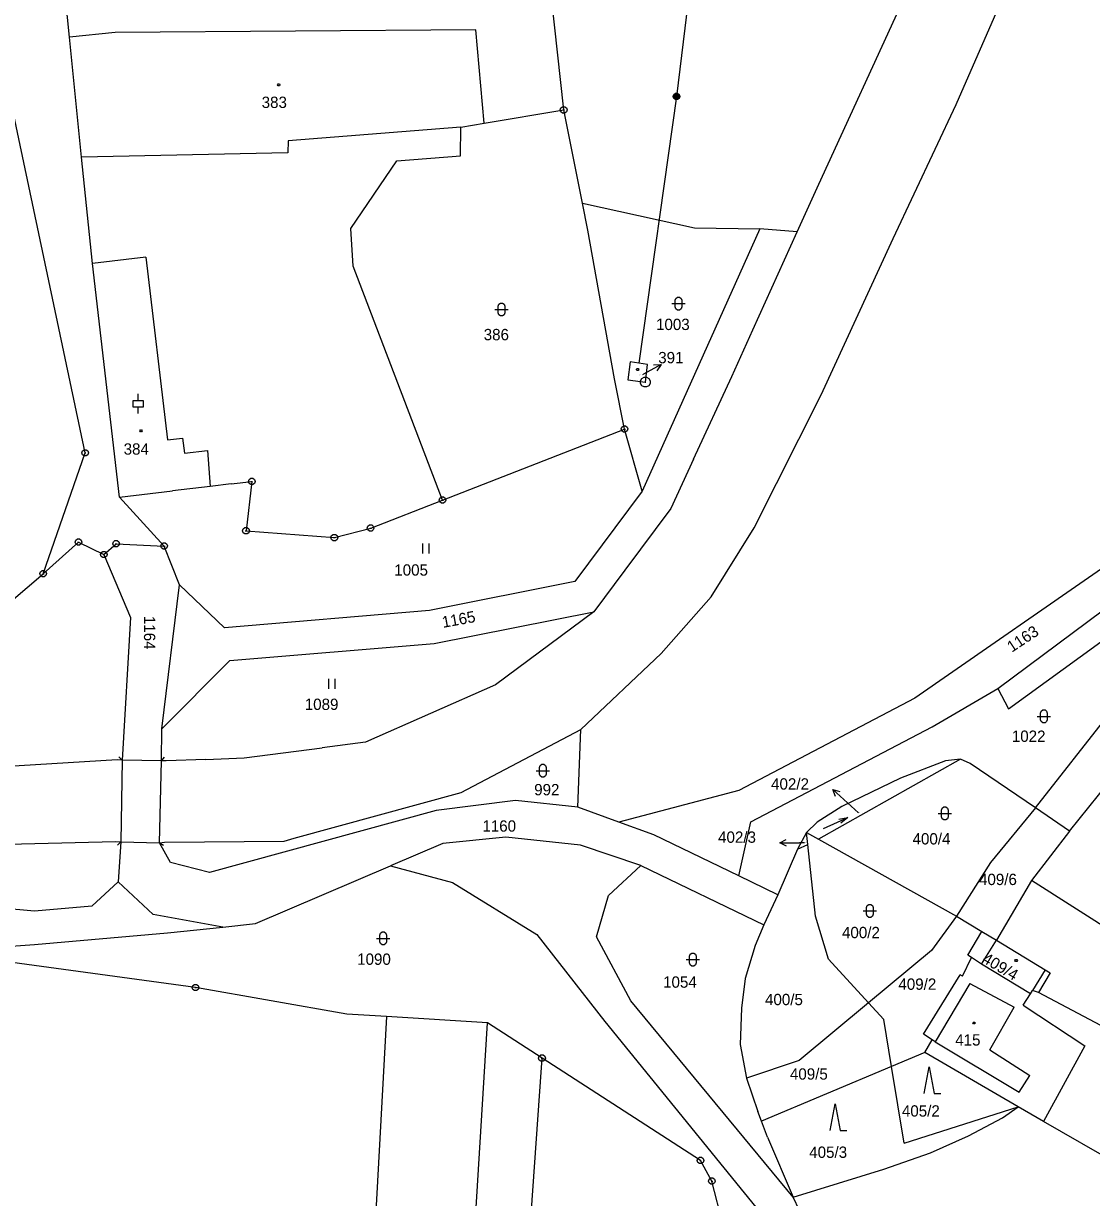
# Model space of a CAD drawing. Extents: x -812394 to -807601, y -1013098 to -1009266.
# Drawn here: x -810997.6 to -810837.1, y -1011688.8 to -1011512.4 of the extents above; entities that cross this region are included whole.
import ezdxf

# ---------------------------------------------------------------- set-up
doc = ezdxf.new("R2010")
doc.units = 0
for name, color, linetype in [('KN_HRANICE', 7, 'Continuous'), ('KN_KULTURY', 7, 'Continuous'), ('KN_MEZNIKY', 7, 'Continuous'), ('KN_PARCELY', 7, 'Continuous'), ('KN_SLUCKY', 7, 'Continuous'), ('KN_VEDENI', 7, 'Continuous')]:
    doc.layers.add(name, color=color, linetype=linetype)

# ---------------------------------------------------------------- blocks, each defined once
blk = doc.blocks.new('101')
blk.add_line((-0.05, 0), (0.05, 0))
blk.add_lwpolyline([(0.19, 0.72), (0.53, 0.53), (0.72, 0.19), (0.72, -0.2), (0.53, -0.54), (0.19, -0.73), (-0.2, -0.73), (-0.54, -0.54), (-0.73, -0.2), (-0.73, 0.19), (-0.54, 0.53), (-0.2, 0.72), (0.19, 0.72)])
blk = doc.blocks.new('306')
for p, q in [((-0.5, 1.5), (-0.5, 0)), ((0.5, 0), (0.5, 1.5))]:
    blk.add_line(p, q)
blk = doc.blocks.new('308')
blk.add_lwpolyline([(-0.75, 0), (0, 4), (0.75, 0), (1.75, 0)])
blk = doc.blocks.new('316')
for points in [[(-0.5, 1.5), (-0.4, 1.79), (-0.15, 1.97), (0.16, 1.97), (0.41, 1.79), (0.51, 1.5), (0.51, 0.5), (0.41, 0.21), (0.16, 0.03), (-0.15, 0.03), (-0.4, 0.21), (-0.5, 0.5), (-0.5, 1.5)], [(-1, 1), (0.27, 1), (1, 1)]]:
    blk.add_lwpolyline(points)
blk = doc.blocks.new('802')
blk.add_line((-3, 0), (3, 0))
blk.add_lwpolyline([(1, 0.5), (3, 0), (1, -0.5)])
blk = doc.blocks.new('10292')
blk.add_line((0, 3), (0, 0))
blk.add_lwpolyline([(-0.5, 2), (0, 3), (0.5, 2)])
blk = doc.blocks.new('318')
blk.add_line((0, 2), (0, 3))
blk.add_lwpolyline([(0, 0), (0, 1), (-0.75, 1), (-0.75, 2), (0, 2), (0.75, 2), (0.75, 1), (0, 1)])
blk = doc.blocks.new('105')
blk.add_line((-0.12, 0), (0.12, 0))
blk.add_lwpolyline([(0.15, 0.48), (0.4, 0.3), (0.5, 0.01), (0.4, -0.28), (0.15, -0.46), (-0.16, -0.46), (-0.41, -0.28), (-0.51, 0.01), (-0.41, 0.3), (-0.16, 0.48), (0.15, 0.48)])
blk = doc.blocks.new('4201')
blk.add_line((0, 0), (-0.5, -0.5))
blk = doc.blocks.new('601')
blk.add_lwpolyline([(-0.15, 0.48), (0.16, 0.48), (0.41, 0.3), (0.51, 0.01), (0.41, -0.28), (0.16, -0.46), (-0.15, -0.46), (-0.4, -0.28), (-0.5, 0.01), (-0.4, 0.3), (-0.15, 0.48), (-0.12, 0.44), (0.12, 0.44), (0.28, 0.36), (-0.28, 0.36), (-0.36, 0.28), (0.36, 0.28), (0.36, 0.2), (-0.36, 0.2), (-0.4, 0.12), (0.4, 0.12), (0.44, 0.04), (-0.44, 0.04), (-0.44, -0.04), (0.44, -0.04), (0.41, -0.12), (-0.4, -0.12), (-0.39, -0.2), (0.42, -0.2), (0.37, -0.28), (-0.35, -0.28), (-0.27, -0.36), (0.29, -0.36), (0.18, -0.44), (-0.16, -0.44)])
blk = doc.blocks.new('402')
blk.add_lwpolyline([(0.09, 0.15), (0.18, 0), (0.09, -0.15), (-0.09, -0.15), (-0.18, 0), (-0.09, 0.15), (0.09, 0.15)])

msp = doc.modelspace()

# ---------------------------------------------------------------- linework, layer by layer
at = {"layer": 'KN_HRANICE'}
for p, q in [((-810990.65, -1011514.5), (-810992.93, -1011491.98)), ((-810878.11, -1011536.55), (-810858.26, -1011493.31)), ((-810988.29, -1011576.92), (-811004.66, -1011499.57)), ((-810916.42, -1011525.41), (-810918.87, -1011502.5)), ((-810983.8, -1011513.77), (-810990.65, -1011514.5)), ((-810988.82, -1011532.52), (-810990.65, -1011514.5)), ((-810929.63, -1011513.38), (-810983.8, -1011513.77)), ((-810928.34, -1011527.4), (-810929.63, -1011513.38)), ((-810928.34, -1011527.4), (-810916.42, -1011525.41)), ((-810913.6, -1011539.41), (-810916.42, -1011525.41)), ((-810931.87, -1011527.99), (-810957.81, -1011530.07)), ((-810931.91, -1011532.3), (-810931.87, -1011527.99)), ((-810931.87, -1011527.99), (-810928.34, -1011527.4)), ((-810957.81, -1011530.07), (-810957.84, -1011531.83)), ((-810957.84, -1011531.83), (-810988.82, -1011532.52)), ((-810987.2, -1011548.48), (-810988.82, -1011532.52)), ((-810941.47, -1011533.07), (-810931.91, -1011532.3)), ((-810948.4, -1011543.24), (-810941.47, -1011533.07)), ((-810881.34, -1011543.7), (-810878.11, -1011536.55)), ((-810913.6, -1011539.41), (-810896.75, -1011543.11)), ((-810912.78, -1011543.48), (-810913.6, -1011539.41)), ((-810948.04, -1011548.87), (-810948.4, -1011543.24)), ((-810908.81, -1011565.82), (-810912.78, -1011543.48)), ((-810886.95, -1011543.28), (-810904.65, -1011582.69)), ((-810896.75, -1011543.11), (-810886.95, -1011543.28)), ((-810888.01, -1011558.44), (-810881.34, -1011543.7)), ((-810881.34, -1011543.7), (-810886.95, -1011543.28)), ((-810983.14, -1011583.56), (-810987.2, -1011548.48)), ((-810934.61, -1011584.01), (-810948.04, -1011548.87)), ((-810907.28, -1011573.34), (-810908.81, -1011565.82)), ((-810934.61, -1011584.01), (-810907.28, -1011573.34)), ((-810904.65, -1011582.69), (-810907.28, -1011573.34)), ((-810994.59, -1011595.07), (-810988.29, -1011576.92)), ((-810896.93, -1011577.89), (-810900.33, -1011585.26)), ((-810966.35, -1011581.58), (-810969.54, -1011581.95)), ((-810966.35, -1011581.58), (-810963.27, -1011581.22)), ((-810963.27, -1011581.22), (-810964.13, -1011588.63)), ((-810983.14, -1011583.56), (-810975.16, -1011582.61)), ((-810976.41, -1011590.91), (-810983.14, -1011583.56)), ((-810969.54, -1011581.95), (-810975.16, -1011582.61)), ((-810904.65, -1011582.69), (-810914.75, -1011596.26)), ((-810945.41, -1011588.22), (-810934.61, -1011584.01)), ((-810900.33, -1011585.26), (-810907.25, -1011594.56)), ((-810964.13, -1011588.63), (-810950.86, -1011589.65)), ((-810950.86, -1011589.65), (-810945.41, -1011588.22)), ((-810994.59, -1011595.07), (-810989.3, -1011590.32)), ((-810989.3, -1011590.32), (-810985.49, -1011592.2)), ((-810985.49, -1011592.2), (-810983.65, -1011590.57)), ((-810983.65, -1011590.57), (-810976.41, -1011590.91)), ((-810985.49, -1011592.2), (-810981.49, -1011601.67)), ((-810974.14, -1011596.72), (-810976.41, -1011590.91)), ((-810831.4, -1011591.35), (-810863.67, -1011613.78)), ((-811020.14, -1011616.85), (-810994.59, -1011595.07)), ((-810907.25, -1011594.56), (-810911.89, -1011600.79)), ((-810851.23, -1011612.3), (-810827.53, -1011594.64)), ((-810976.79, -1011618.38), (-810974.14, -1011596.72)), ((-810967.38, -1011603.18), (-810974.14, -1011596.72)), ((-810914.75, -1011596.26), (-810936.59, -1011600.58)), ((-810849.63, -1011615.36), (-810824.29, -1011596.97)), ((-810936.59, -1011600.58), (-810967.38, -1011603.18)), ((-810935.89, -1011605.54), (-810911.89, -1011600.79)), ((-810981.49, -1011601.67), (-810982.75, -1011623.07)), ((-810966.54, -1011608.13), (-810935.89, -1011605.54)), ((-810976.79, -1011618.38), (-810966.54, -1011608.13)), ((-810861.07, -1011618.06), (-810851.23, -1011612.3)), ((-810851.23, -1011612.3), (-810849.63, -1011615.36)), ((-810863.67, -1011613.78), (-810890.13, -1011627.65)), ((-810840.43, -1011633.72), (-810825.11, -1011614.6)), ((-810976.85, -1011623.16), (-810976.79, -1011618.38)), ((-810914.28, -1011630.13), (-810913.82, -1011618.49)), ((-810888.31, -1011632.34), (-810861.07, -1011618.06)), ((-810976.85, -1011623.16), (-810982.75, -1011623.07)), ((-810856.83, -1011622.91), (-810878.14, -1011634.96)), ((-810859.07, -1011623.17), (-810865.83, -1011625.76)), ((-810856.83, -1011622.91), (-810859.07, -1011623.17)), ((-810855.38, -1011623.6), (-810856.83, -1011622.91)), ((-810845.57, -1011630.24), (-810855.38, -1011623.6)), ((-810865.83, -1011625.76), (-810874.64, -1011630.05)), ((-810890.13, -1011627.65), (-810908.12, -1011632.39)), ((-810923.64, -1011629.14), (-810935.55, -1011630.66)), ((-810914.28, -1011630.13), (-810923.64, -1011629.14)), ((-810935.55, -1011630.66), (-810969.6, -1011639.97)), ((-810908.12, -1011632.39), (-810914.28, -1011630.13)), ((-810874.64, -1011630.05), (-810878.34, -1011632.37)), ((-810845.57, -1011630.24), (-810852.3, -1011638.43)), ((-810840.43, -1011633.72), (-810845.57, -1011630.24)), ((-810902.89, -1011634.32), (-810908.12, -1011632.39)), ((-810890.13, -1011640.47), (-810888.31, -1011632.34)), ((-810878.34, -1011632.37), (-810879.94, -1011633.96)), ((-810925.1, -1011634.66), (-810934.57, -1011635.58)), ((-810913.89, -1011635.85), (-810925.1, -1011634.66)), ((-810890.13, -1011640.47), (-810902.89, -1011634.32)), ((-810879.94, -1011633.96), (-810881.3, -1011636.47)), ((-810879.75, -1011635.73), (-810879.94, -1011633.96)), ((-810879.94, -1011633.96), (-810878.14, -1011634.96)), ((-810840.43, -1011633.72), (-810846.16, -1011641.14)), ((-810982.94, -1011635.34), (-810983.35, -1011641.36)), ((-810982.94, -1011635.34), (-810977.14, -1011635.5)), ((-810975.48, -1011638.44), (-810977.14, -1011635.5)), ((-810934.57, -1011635.58), (-810942.44, -1011638.95)), ((-810904.85, -1011638.92), (-810913.89, -1011635.85)), ((-810881.3, -1011636.47), (-810884.27, -1011643.3)), ((-810881.3, -1011636.47), (-810879.75, -1011635.73)), ((-810878.58, -1011646.5), (-810879.75, -1011635.73)), ((-810878.14, -1011634.96), (-810857.44, -1011646.51)), ((-810969.6, -1011639.97), (-810975.48, -1011638.44)), ((-810962.69, -1011647.62), (-810942.44, -1011638.95)), ((-810942.44, -1011638.95), (-810933.12, -1011641.48)), ((-810909.69, -1011643.43), (-810904.85, -1011638.92)), ((-810904.85, -1011638.92), (-810886.34, -1011647.79)), ((-810852.3, -1011638.43), (-810857.44, -1011646.51)), ((-810983.35, -1011641.36), (-810987.28, -1011645)), ((-810978.06, -1011646.24), (-810983.35, -1011641.36)), ((-810933.12, -1011641.48), (-810920.45, -1011649.26)), ((-810884.27, -1011643.3), (-810890.13, -1011640.47)), ((-810846.16, -1011641.14), (-810851.41, -1011650.14)), ((-810825.68, -1011654.24), (-810846.16, -1011641.14)), ((-810911.51, -1011649.61), (-810909.69, -1011643.43)), ((-810884.27, -1011643.3), (-810886.34, -1011647.79)), ((-810995.89, -1011645.77), (-811016.44, -1011643.9)), ((-810987.28, -1011645), (-810995.89, -1011645.77)), ((-810967.59, -1011648.15), (-810978.06, -1011646.24)), ((-810876.64, -1011652.99), (-810878.58, -1011646.5)), ((-810857.44, -1011646.51), (-810861.19, -1011651.67)), ((-810857.44, -1011646.51), (-810853.61, -1011648.83)), ((-810975.92, -1011649.01), (-810967.59, -1011648.15)), ((-810967.59, -1011648.15), (-810962.69, -1011647.62)), ((-810886.34, -1011647.79), (-810887.64, -1011650.91)), ((-810855.74, -1011652.37), (-810853.61, -1011648.83)), ((-810853.61, -1011648.83), (-810851.41, -1011650.14)), ((-810995.89, -1011650.79), (-810975.92, -1011649.01)), ((-810920.45, -1011649.26), (-810910.24, -1011662.33)), ((-810906.32, -1011659.22), (-810911.51, -1011649.61)), ((-810851.41, -1011650.14), (-810844.12, -1011654.56)), ((-811011.38, -1011651.85), (-810995.89, -1011650.79)), ((-810971.7, -1011657.24), (-811011.38, -1011651.85)), ((-810887.64, -1011650.91), (-810889.14, -1011655.88)), ((-810861.19, -1011651.67), (-810870.64, -1011659.53)), ((-810855.16, -1011652.74), (-810855.74, -1011652.37)), ((-810870.64, -1011659.53), (-810876.64, -1011652.99)), ((-810856.54, -1011655.55), (-810855.16, -1011652.74)), ((-810853.65, -1011653.71), (-810855.16, -1011652.74)), ((-810846.33, -1011658.17), (-810853.65, -1011653.71)), ((-810889.14, -1011655.88), (-810889.71, -1011660.31)), ((-810862.38, -1011664.26), (-810856.89, -1011655.34)), ((-810856.54, -1011655.55), (-810856.89, -1011655.34)), ((-810843.35, -1011655.03), (-810845.13, -1011657.96)), ((-810844.12, -1011654.56), (-810843.35, -1011655.03)), ((-810948.98, -1011661.21), (-810971.7, -1011657.24)), ((-810846.33, -1011658.17), (-810846.01, -1011657.66)), ((-810845.13, -1011657.96), (-810846.01, -1011657.66)), ((-810881.94, -1011688.74), (-810906.32, -1011659.22)), ((-810847.39, -1011659.86), (-810846.33, -1011658.17)), ((-810820.6, -1011671.03), (-810845.13, -1011657.96)), ((-810943.04, -1011661.57), (-810948.98, -1011661.21)), ((-810889.71, -1011660.31), (-810889.93, -1011665.8)), ((-810870.64, -1011659.53), (-810881.07, -1011668.21)), ((-810868.35, -1011662.02), (-810870.64, -1011659.53)), ((-810847.39, -1011659.86), (-810838.13, -1011666.01)), ((-810927.88, -1011662.52), (-810943.04, -1011661.57)), ((-810919.67, -1011667.84), (-810927.88, -1011662.52)), ((-810910.24, -1011662.33), (-810885.61, -1011692.65)), ((-810867.17, -1011669.11), (-810868.35, -1011662.02)), ((-810861.06, -1011665.11), (-810862.38, -1011664.26)), ((-810889.93, -1011665.8), (-810888.97, -1011670.87)), ((-810862.16, -1011667.01), (-810861.06, -1011665.11)), ((-810838.13, -1011666.01), (-810844.35, -1011677.34)), ((-810923.04, -1011716.62), (-810919.67, -1011667.84)), ((-810895.87, -1011683.21), (-810919.67, -1011667.84)), ((-810881.07, -1011668.21), (-810888.97, -1011670.87)), ((-810862.16, -1011667.01), (-810867.17, -1011669.11)), ((-810848.18, -1011675.13), (-810862.16, -1011667.01)), ((-810867.17, -1011669.11), (-810886.7, -1011677.32)), ((-810865.26, -1011680.6), (-810867.17, -1011669.11)), ((-810888.97, -1011670.87), (-810887.26, -1011675.84)), ((-810865.26, -1011680.6), (-810848.18, -1011675.13)), ((-810850.5, -1011676.82), (-810848.18, -1011675.13)), ((-810844.35, -1011677.34), (-810848.18, -1011675.13)), ((-810886.7, -1011677.32), (-810887.26, -1011675.84)), ((-810855.6, -1011679.52), (-810850.5, -1011676.82)), ((-810885.79, -1011679.69), (-810886.7, -1011677.32)), ((-810828.27, -1011686.59), (-810844.35, -1011677.34)), ((-810885.79, -1011679.69), (-810881.94, -1011688.74)), ((-810861.34, -1011682.08), (-810855.6, -1011679.52)), ((-810868.35, -1011684.5), (-810861.34, -1011682.08)), ((-810894.15, -1011686.31), (-810895.87, -1011683.21)), ((-810881.94, -1011688.74), (-810868.35, -1011684.5)), ((-810889.63, -1011703.76), (-810894.15, -1011686.31)), ((-810875.9, -1011701.34), (-810881.94, -1011688.74))]:
    msp.add_line(p, q, dxfattribs=at)
for points in [[(-810887.79, -1011588.2), (-810877.76, -1011568.21), (-810866.95, -1011544.7), (-810857.48, -1011524.61), (-810845.94, -1011498.21), (-810817.11, -1011436.78)], [(-810896.93, -1011577.89), (-810891.18, -1011565.46), (-810888.01, -1011558.44)], [(-810913.82, -1011618.49), (-810901.8, -1011607.05), (-810894.25, -1011598.54), (-810887.79, -1011588.2)], [(-810845.57, -1011630.24), (-810834.41, -1011616.01), (-810814.84, -1011590.15)], [(-810911.89, -1011600.79), (-810926.65, -1011611.75), (-810946.18, -1011620.4), (-810952.71, -1011621.24)], [(-810956.88, -1011634.82), (-810931.83, -1011627.95), (-810913.82, -1011618.49)], [(-810970.17, -1011622.97), (-810964.43, -1011622.75), (-810952.71, -1011621.24)], [(-810982.75, -1011623.07), (-810983.49, -1011623.04), (-811005.6, -1011624.4)], [(-810970.17, -1011622.97), (-810976.1, -1011623.19), (-810976.85, -1011623.16)], [(-811029.29, -1011645.78), (-811020.71, -1011639.62), (-811010, -1011635.94), (-810983.72, -1011635.29), (-810982.94, -1011635.34)], [(-810977.14, -1011635.5), (-810976.39, -1011635.39), (-810958.42, -1011635.24), (-810956.88, -1011634.82)]]:
    msp.add_lwpolyline(points, dxfattribs=at)
msp.add_lwpolyline([(-810906.8, -1011565.95), (-810904.15, -1011566.29), (-810903.81, -1011563.64), (-810906.45, -1011563.25)], close=True, dxfattribs=at)
at = {"layer": 'KN_PARCELY'}
for p, q in [((-810904.55, -1011565.14), (-810904.44, -1011565.08)), ((-810872.12, -1011630.99), (-810873.78, -1011629.5)), ((-810880.24, -1011635.49), (-810880.98, -1011635.49))]:
    msp.add_line(p, q, dxfattribs=at)
at = {"layer": 'KN_SLUCKY'}
for p, q in [((-810979.2, -1011547.53), (-810987.2, -1011548.48)), ((-810979.2, -1011547.53), (-810975.94, -1011574.98)), ((-810975.94, -1011574.98), (-810973.66, -1011574.71)), ((-810973.66, -1011574.71), (-810973.39, -1011576.98)), ((-810973.39, -1011576.98), (-810969.94, -1011576.57)), ((-810969.94, -1011576.57), (-810969.54, -1011581.95)), ((-810982.75, -1011623.07), (-810982.94, -1011635.34)), ((-810977.14, -1011635.5), (-810976.85, -1011623.16)), ((-810853.65, -1011653.71), (-810851.41, -1011650.14)), ((-810844.12, -1011654.56), (-810846.01, -1011657.66)), ((-810855.41, -1011656.64), (-810860.65, -1011665.37)), ((-810855.41, -1011656.64), (-810848.77, -1011660.2)), ((-810852.43, -1011666.59), (-810848.77, -1011660.2)), ((-810943.04, -1011661.57), (-810945.82, -1011712.25)), ((-810931.06, -1011715.46), (-810927.88, -1011662.52)), ((-810860.65, -1011665.37), (-810861.06, -1011665.11)), ((-810860.65, -1011665.37), (-810848.03, -1011672.95)), ((-810852.43, -1011666.59), (-810846.42, -1011670.43)), ((-810848.03, -1011672.95), (-810846.42, -1011670.43))]:
    msp.add_line(p, q, dxfattribs=at)
at = {"layer": 'KN_VEDENI'}
msp.add_lwpolyline([(-810881.42, -1011374.93), (-810888.67, -1011434.63), (-810899.49, -1011523.39), (-810905.13, -1011563.44)], dxfattribs=at)

# ---------------------------------------------------------------- block references
at = {"layer": 'KN_KULTURY'}
for name, p in [('402', (-810959.21, -1011521.65)), ('316', (-810899.19, -1011555.5)), ('316', (-810925.75, -1011556.38)), ('402', (-810905.32, -1011564.38)), ('318', (-810980.31, -1011571.03)), ('402', (-810979.91, -1011573.6)), ('306', (-810937.11, -1011592.02)), ('306', (-810951.22, -1011612.37)), ('316', (-810844.29, -1011617.5)), ('316', (-810919.55, -1011625.66)), ('316', (-810859.18, -1011632.08)), ('316', (-810870.44, -1011646.72)), ('316', (-810943.55, -1011650.85)), ('316', (-810897.03, -1011654.03)), ('402', (-810848.46, -1011653.19)), ('402', (-810854.78, -1011662.56)), ('308', (-810861.51, -1011673.14)), ('308', (-810875.65, -1011678.71))]:
    msp.add_blockref(name, p, dxfattribs=at)
at = {"layer": 'KN_KULTURY', "xscale": 0.67, "yscale": 0.67, "rotation": 24.637185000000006}
msp.add_blockref('802', (-810875.56, -1011632.52), dxfattribs=at)
at = {"layer": 'KN_MEZNIKY'}
for name, p in [('105', (-810916.42, -1011525.41)), ('101', (-810904.15, -1011566.29)), ('105', (-810907.28, -1011573.34)), ('105', (-810988.29, -1011576.92)), ('105', (-810963.27, -1011581.22)), ('105', (-810934.61, -1011584.01)), ('105', (-810964.13, -1011588.63)), ('105', (-810945.41, -1011588.22)), ('105', (-810989.3, -1011590.32)), ('105', (-810983.65, -1011590.57)), ('105', (-810976.41, -1011590.91)), ('105', (-810950.86, -1011589.65)), ('105', (-810985.49, -1011592.2)), ('105', (-810994.59, -1011595.07)), ('105', (-810971.7, -1011657.24)), ('105', (-810919.67, -1011667.84)), ('105', (-810895.87, -1011683.21)), ('105', (-810894.15, -1011686.31))]:
    msp.add_blockref(name, p, dxfattribs=at)
at = {"layer": 'KN_PARCELY'}
for p, rotation in [((-810904.44, -1011565.08), -61.71817200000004), ((-810873.78, -1011629.5), 48.185750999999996), ((-810880.98, -1011635.49), 90.01166999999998)]:
    msp.add_blockref('10292', p, dxfattribs=dict(at, rotation=rotation))
at = {"layer": 'KN_SLUCKY'}
for p, rotation in [((-810982.75, -1011623.07), -90.07958300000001), ((-810976.85, -1011623.16), -178.02860400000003), ((-810977.14, -1011635.5), 105.53882599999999)]:
    msp.add_blockref('4201', p, dxfattribs=dict(at, rotation=rotation))
msp.add_blockref('4201', (-810982.94, -1011635.34), dxfattribs=at)
at = {"layer": 'KN_VEDENI'}
msp.add_blockref('601', (-810899.49, -1011523.39), dxfattribs=at)

# ---------------------------------------------------------------- texts
at = {"layer": 'KN_PARCELY'}
for s, height, p in [('383', 1.7, (-810961.78, -1011525.11)), ('1003', 1.7, (-810902.55, -1011558.47)), ('386', 1.7, (-810928.43, -1011560)), ('391', 1.7, (-810902.22, -1011563.46)), ('391', 0.1, (-810905.12, -1011565.29)), ('384', 1.7, (-810982.51, -1011577.19)), ('1005', 1.7, (-810941.86, -1011595.36)), ('1089', 1.7, (-810955.31, -1011615.54)), ('1022', 1.7, (-810849.11, -1011620.33)), ('402/2', 1.7, (-810885.27, -1011627.5)), ('992', 1.7, (-810920.85, -1011628.36)), ('402/2', 0.1, (-810872.36, -1011630.99)), ('1160', 1.7, (-810928.63, -1011633.82)), ('402/3', 1.7, (-810893.23, -1011635.49)), ('400/4', 1.7, (-810864.02, -1011635.74)), ('402/3', 0.1, (-810880.48, -1011635.49)), ('409/6', 1.7, (-810854.04, -1011641.84)), ('400/2', 1.7, (-810874.62, -1011649.82)), ('1090', 1.7, (-810947.44, -1011653.82)), ('1054', 1.7, (-810901.49, -1011657.26)), ('409/2', 1.7, (-810866.15, -1011657.57)), ('400/5', 1.7, (-810886.18, -1011659.88)), ('415', 1.7, (-810857.61, -1011665.95)), ('409/5', 1.7, (-810882.44, -1011671.07)), ('405/2', 1.7, (-810865.62, -1011676.62)), ('405/3', 1.7, (-810879.54, -1011682.82))]:
    msp.add_text(s, height=height, dxfattribs=at).set_placement(p)
for s, rotation, p in [('1165', 10.313, (-810934.54, -1011603.21)), ('1164', 269.978, (-810979.46, -1011601.41)), ('1163', 33.403, (-810849.12, -1011606.95)), ('409/4', 329.279, (-810853.7, -1011653.35))]:
    msp.add_text(s, height=1.7, rotation=rotation, dxfattribs=at).set_placement(p)

doc.saveas('drawing.dxf')
